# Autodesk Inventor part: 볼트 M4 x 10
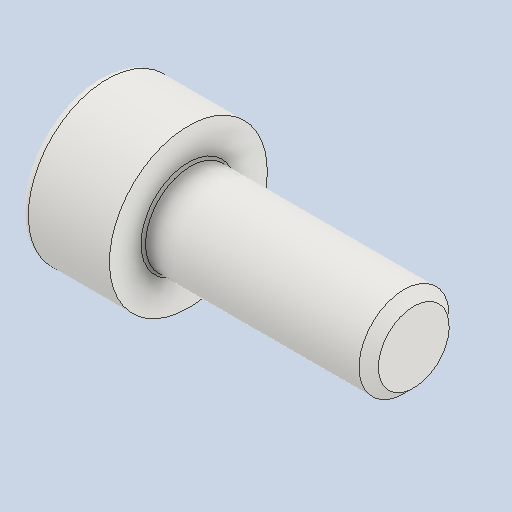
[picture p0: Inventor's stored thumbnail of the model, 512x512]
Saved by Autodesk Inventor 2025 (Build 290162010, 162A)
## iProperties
Created: 2024-07
Part Number: 볼트 M4 x 10
Material: 강철, 연강
Description: 6각머리 태핑 나사
Document SubType Name: Modeling
Designer: 학생
Density: 7.86 g/cm^3
Appearance: 기본값
Author: jhkim
Revision Number: 1
Sending System: Autodesk Inventor 2025
Preprocessor: ST-DEVELOPER v20
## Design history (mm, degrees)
feature "Solid1"
node "솔리드1"
